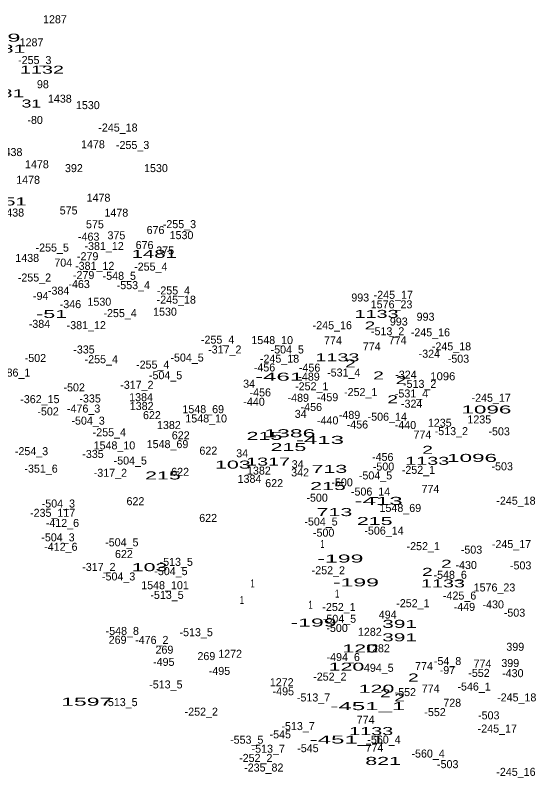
# Model space of a CAD drawing. Extents: x -660434 to -656144, y -997850 to -994016.
# Drawn here: x -658769.3 to -658508.8, y -995192.7 to -994814.9 of the extents above; entities that cross this region are included whole.
import ezdxf
from ezdxf.enums import TextEntityAlignment as Align

# ---------------------------------------------------------------- set-up
doc = ezdxf.new("R2010")
doc.units = 0
doc.header["$LTSCALE"] = 1.6
doc.layers.add('24', color=7, linetype='Continuous')

msp = doc.modelspace()

# ---------------------------------------------------------------- texts
at = {"layer": '24'}
for s, p in [('1287', (-658749.406, -994818.97)), ('1287', (-658761.116, -994830.5)), ('-255_3', (-658759.512, -994839.38)), ('98', (-658755.433, -994851.45)), ('1438', (-658746.944, -994858.67)), ('1530', (-658732.944, -994861.9)), ('-80', (-658759.309, -994869.31)), ('-245_18', (-658717.879, -994873.1)), ('1478', (-658730.39, -994881.47)), ('-255_3', (-658710.542, -994881.83)), ('1438', (-658771.624, -994885.37)), ('1478', (-658758.42, -994891.46)), ('392', (-658739.913, -994893.39)), ('1530', (-658698.864, -994893.38)), ('1478', (-658762.83, -994899.24)), ('1478', (-658727.6, -994908.17)), ('575', (-658742.543, -994914.54)), ('1438', (-658770.764, -994915.6)), ('1478', (-658718.67, -994915.66)), ('575', (-658729.393, -994921.45)), ('-255_3', (-658687.122, -994921.39)), ('676', (-658699.083, -994924.33)), ('-463', (-658732.515, -994927.64)), ('375', (-658718.643, -994926.96)), ('1530', (-658686.094, -994926.89)), ('-255_5', (-658750.752, -994933.1)), ('-381_12', (-658724.799, -994932.33)), ('676', (-658704.563, -994931.82)), ('-279', (-658733.015, -994937.43)), ('375', (-658694.263, -994934.54)), ('1438', (-658763.264, -994938.27)), ('704', (-658745.241, -994940.63)), ('-381_12', (-658729.499, -994942.23)), ('-255_4', (-658701.447, -994942.62)), ('-255_2', (-658759.642, -994948.07)), ('-279', (-658735.035, -994946.84)), ('-548_5', (-658717.197, -994947.22)), ('-463', (-658737.315, -994951.35)), ('-553_4', (-658710.177, -994951.88)), ('-384', (-658747.549, -994954.62)), ('-255_4', (-658690.137, -994954.54)), ('-94', (-658756.515, -994957.29)), ('-245_18', (-658688.699, -994959.15)), ('993', (-658596.678, -994958.07)), ('-245_17', (-658580.135, -994956.72)), ('-346', (-658741.655, -994961.38)), ('1530', (-658727.174, -994960.17)), ('1576_23', (-658581.009, -994961.47)), ('-255_4', (-658716.807, -994965.86)), ('1530', (-658694.344, -994965.16)), ('-384', (-658757.149, -994971.23)), ('993', (-658577.378, -994970.08)), ('993', (-658563.998, -994967.67)), ('-381_12', (-658733.719, -994971.88)), ('-245_16', (-658610.645, -994971.91)), ('-513_2', (-658582.976, -994974.92)), ('-245_16', (-658561.585, -994975.47)), ('-255_4', (-658668.037, -994979.12)), ('1548_10', (-658640.72, -994979.35)), ('774', (-658610.303, -994979.5)), ('774', (-658590.903, -994982.48)), ('774', (-658577.953, -994979.41)), ('-245_18', (-658551.019, -994982.48)), ('-335', (-658734.875, -994984.04)), ('-317_2', (-658664.442, -994984.04)), ('-504_5', (-658633.191, -994984.04)), ('-324', (-658562.099, -994986.17)), ('-502', (-658759.159, -994988.28)), ('-255_4', (-658726.217, -994988.91)), ('-504_5', (-658683.301, -994988.08)), ('-245_18', (-658637.039, -994988.62)), ('-503', (-658547.529, -994988.66)), ('-255_4', (-658700.487, -994991.6)), ('-456', (-658644.555, -994993.02)), ('-456', (-658621.995, -994993.12)), ('-486_1', (-658770.036, -994995.59)), ('-504_5', (-658694.051, -994996.91)), ('-489', (-658622.285, -994997.62)), ('-531_4', (-658604.91, -994995.56)), ('-324', (-658573.809, -994996.63)), ('34', (-658652.271, -995001.15)), ('-513_2', (-658566.936, -995001.23)), ('-502', (-658739.769, -995002.97)), ('-317_2', (-658708.412, -995001.71)), ('-252_1', (-658620.926, -995002.43)), ('-252_1', (-658596.436, -995005.32)), ('-362_15', (-658756.941, -995008.87)), ('-335', (-658731.805, -995008.53)), ('1384', (-658706.314, -995007.88)), ('-456', (-658646.675, -995005.5)), ('-489', (-658627.665, -995008.19)), ('-459', (-658613.025, -995007.9)), ('-531_4', (-658571.02, -995006.02)), ('-245_17', (-658531.175, -995008.19)), ('1382', (-658706.02, -995012.31)), ('-440', (-658649.797, -995010.18)), ('-456', (-658621.135, -995012.8)), ('-324', (-658570.929, -995011.14)), ('-502', (-658752.819, -995014.98)), ('-476_3', (-658735.048, -995013.57)), ('1548_69', (-658675.223, -995013.88)), ('34', (-658626.451, -995016.23)), ('-489', (-658602.035, -995016.73)), ('-504_3', (-658732.811, -995019.6)), ('622', (-658700.883, -995016.86)), ('1548_10', (-658673.75, -995018.53)), ('-440', (-658612.947, -995019.5)), ('-506_14', (-658583.159, -995017.65)), ('1235', (-658537.11, -995019.02)), ('1382', (-658692.39, -995021.81)), ('-456', (-658598.095, -995021.54)), ('-440', (-658574.077, -995021.8)), ('1235', (-658556.88, -995020.66)), ('-255_4', (-658722.187, -995025.41)), ('622', (-658686.473, -995026.94)), ('774', (-658565.563, -995026.56)), ('-513_2', (-658551.096, -995024.85)), ('-503', (-658527.179, -995024.96)), ('1548_69', (-658693.083, -995031.35)), ('-254_3', (-658761.117, -995034.86)), ('1548_10', (-658719.64, -995031.98)), ('622', (-658672.663, -995034.62)), ('-335', (-658730.365, -995036.27)), ('34', (-658655.731, -995035.92)), ('-456', (-658585.415, -995037.77)), ('-504_5', (-658711.721, -995039.55)), ('34', (-658627.981, -995041.39)), ('-500', (-658585.023, -995042.56)), ('-503', (-658525.649, -995042.44)), ('-351_6', (-658756.352, -995043.6)), ('-317_2', (-658721.662, -995045.68)), ('622', (-658686.773, -995045.19)), ('1382', (-658647.37, -995044.57)), ('342', (-658626.751, -995045.49)), ('-252_1', (-658567.556, -995044.21)), ('1384', (-658652.064, -995048.7)), ('-500', (-658605.753, -995050.44)), ('-504_5', (-658589.031, -995046.99)), ('622', (-658639.733, -995050.86)), ('774', (-658561.533, -995053.74)), ('-500', (-658618.243, -995058.12)), ('-506_14', (-658591.509, -995055.07)), ('-504_3', (-658747.691, -995061.03)), ('622', (-658709.133, -995059.88)), ('-245_18', (-658518.769, -995059.62)), ('-235_117', (-658750.545, -995065.68)), ('1548_69', (-658576.613, -995063.24)), ('622', (-658672.753, -995068.24)), ('-412_6', (-658745.666, -995070.76)), ('-504_5', (-658616.291, -995070.04)), ('-500', (-658614.973, -995075.6)), ('-506_14', (-658584.789, -995074.58)), ('-504_3', (-658747.881, -995077.93)), ('-504_5', (-658715.941, -995080.43)), ('-412_6', (-658746.436, -995082.66)), ('-252_1', (-658565.156, -995082.34)), ('-503', (-658541.009, -995084.1)), ('-245_17', (-658520.995, -995081.3)), ('622', (-658714.893, -995086.29)), ('-513_5', (-658688.726, -995090.19)), ('-430', (-658543.663, -995091.78)), ('-503', (-658516.429, -995091.97)), ('-317_2', (-658727.422, -995092.73)), ('-504_5', (-658691.371, -995094.83)), ('-252_2', (-658612.632, -995094.4)), ('-504_3', (-658717.541, -995097.49)), ('-548_6', (-658551.672, -995096.67)), ('1548_101', (-658694.343, -995101.86)), ('1576_23', (-658529.519, -995102.98)), ('-513_5', (-658693.336, -995106.72)), ('-425_6', (-658546.962, -995107.05)), ('-252_1', (-658570.336, -995110.85)), ('-252_1', (-658607.296, -995112.77)), ('-449', (-658544.559, -995112.7)), ('-430', (-658530.133, -995111.46)), ('-504_5', (-658607.071, -995118.64)), ('494', (-658582.941, -995116.56)), ('-503', (-658519.499, -995115.59)), ('-548_8', (-658715.707, -995124.72)), ('-513_5', (-658678.746, -995125.35)), ('-500', (-658608.253, -995123.23)), ('1282', (-658591.88, -995125.17)), ('269', (-658718.048, -995129.14)), ('-476_2', (-658700.948, -995129.22)), ('1282', (-658587.81, -995133.38)), ('399', (-658519.118, -995132.64)), ('269', (-658694.618, -995134.09)), ('269', (-658673.658, -995137.31)), ('1272', (-658661.776, -995136.14)), ('-495', (-658694.955, -995140.2)), ('-494_6', (-658605.182, -995137.78)), ('-54_8', (-658552.987, -995139.78)), ('774', (-658535.513, -995141.05)), ('399', (-658521.618, -995140.76)), ('-495', (-658667.115, -995144.71)), ('-494_5', (-658588.286, -995143.15)), ('774', (-658564.793, -995142.3)), ('-97', (-658553.055, -995144.28)), ('-252_2', (-658611.872, -995147.56)), ('-552', (-658537.265, -995145.7)), ('-430', (-658520.343, -995145.83)), ('-513_5', (-658693.906, -995151.46)), ('1272', (-658635.956, -995150.35)), ('-546_1', (-658539.716, -995152.52)), ('-495', (-658635.155, -995154.89)), ('-552', (-658574.125, -995155.3)), ('774', (-658561.433, -995153.53)), ('-513_5', (-658716.376, -995160.3)), ('-513_7', (-658620.032, -995157.98)), ('-245_18', (-658518.379, -995157.95)), ('728', (-658550.653, -995160.6)), ('-252_2', (-658676.192, -995165.09)), ('-552', (-658559.245, -995165.29)), ('-503', (-658532.369, -995166.92)), ('774', (-658593.983, -995169.09)), ('-513_7', (-658627.772, -995172.28)), ('-245_17', (-658528.105, -995173.52)), ('-553_5', (-658653.452, -995179.1)), ('-545', (-658636.679, -995176.41)), ('-560_4', (-658584.796, -995179.01)), ('-513_7', (-658642.692, -995183.6)), ('-545', (-658622.839, -995183.33)), ('774', (-658589.563, -995183.12)), ('-560_4', (-658562.716, -995186.02)), ('-252_2', (-658648.932, -995188.2)), ('-235_82', (-658644.921, -995193)), ('-503', (-658552.909, -995191.32)), ('-245_16', (-658518.775, -995195.16))]:
    msp.add_text(s, height=4, dxfattribs=at).set_placement(p, align=Align.CENTER)
for s, width, p in [('-139', 2.2, (-658778.425, -994828.19)), ('-81', 2, (-658771.901, -994833.7)), ('1132', 1.85, (-658755.904, -994844.19)), ('-81', 2, (-658772.381, -994855.98)), ('31', 1.65, (-658761.187, -994861.09)), ('1351', 1.85, (-658774.624, -994910.03)), ('1481', 1.9, (-658699.729, -994936.24)), ('-51', 2, (-658751.041, -994966.29)), ('1133', 1.85, (-658588.514, -994966.26)), ('2', 1.8, (-658591.791, -994972.04)), ('1133', 1.85, (-658608.094, -994987.96)), ('2', 1.8, (-658601.581, -994991.04)), ('-461', 2.25, (-658637.221, -994997.64)), ('2', 1.8, (-658587.561, -994997)), ('1096', 1.05, (-658555.35, -994997.42)), ('2', 1.8, (-658576.241, -994999.32)), ('2', 1.8, (-658580.461, -995008.91)), ('1096', 2.1, (-658533.543, -995014.04)), ('215', 2, (-658644.597, -995027.23)), ('1386', 2.15, (-658631.883, -995025.9)), ('-413', 2.25, (-658616.816, -995029.24)), ('215', 2, (-658632.597, -995032.8)), ('2', 1.8, (-658562.991, -995034.2)), ('1096', 2.1, (-658540.733, -995038.24)), ('103', 2, (-658660.404, -995041.57)), ('1317', 1.85, (-658642.749, -995040.08)), ('1133', 1.85, (-658563.164, -995039.69)), ('713', 2, (-658612.093, -995043.72)), ('215', 2, (-658695.377, -995047.01)), ('215', 2, (-658612.817, -995052.3)), ('-413', 2.25, (-658587.486, -995059.72)), ('713', 2, (-658609.593, -995065.32)), ('215', 2, (-658589.427, -995069.77)), ('1', 0.65, (-658615.587, -995081.28)), ('-199', 2.15, (-658606.609, -995088.54)), ('2', 1.8, (-658553.581, -995091.15)), ('103', 2, (-658702.064, -995092.85)), ('2', 1.8, (-658563.091, -995095.19)), ('1', 0.65, (-658650.537, -995100.97)), ('-199', 2.15, (-658598.829, -995100.45)), ('1133', 1.85, (-658555.294, -995100.96)), ('1', 0.65, (-658608.197, -995106.06)), ('1', 0.65, (-658655.817, -995109.23)), ('1', 0.65, (-658621.547, -995111.63)), ('-199', 2.15, (-658620.049, -995120.52)), ('391', 1.95, (-658576.983, -995121.18)), ('391', 1.95, (-658576.993, -995127.9)), ('120', 2, (-658596.684, -995133.49)), ('120', 2, (-658603.554, -995142.6)), ('2', 1.8, (-658570.091, -995148)), ('120', 2, (-658588.534, -995153.6)), ('2', 1.8, (-658584.111, -995155.89)), ('1597', 2.15, (-658733.497, -995160.1)), ('2', 1.8, (-658577.001, -995157.99)), ('-451_1', 2.25, (-658592.853, -995162.3)), ('1133', 1.85, (-658591.204, -995174.77)), ('-451_1', 2.25, (-658603.223, -995179.01)), ('821', 2, (-658585.217, -995189.69))]:
    msp.add_text(s, height=4, dxfattribs=dict(at, width=width)).set_placement(p, align=Align.CENTER)

doc.saveas('drawing.dxf')
